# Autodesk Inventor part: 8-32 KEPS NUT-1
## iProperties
Created: 2007-09
Part Number: 8-32 KEPS NUT-1
Document SubType Name: Modeling
Material: Stainless Steel
Density: 8.08 g/cm^3
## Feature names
1. Base1
